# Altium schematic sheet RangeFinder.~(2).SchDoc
size A
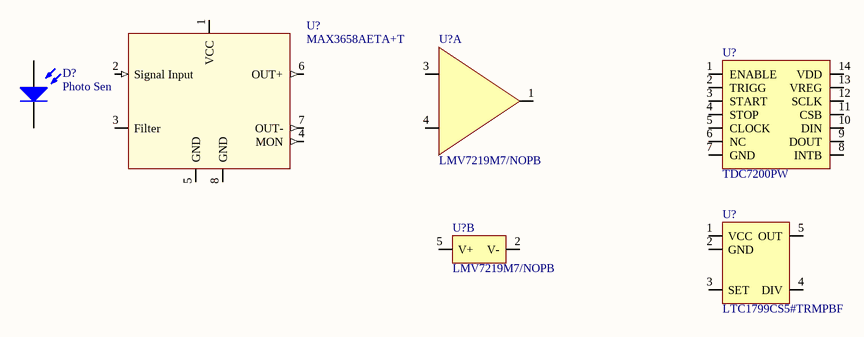
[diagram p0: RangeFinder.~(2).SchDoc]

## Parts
(Parts that share a designator on the sheet are numbered #1, #2 ... from top to bottom, then left to right.)
D?  Photo Sen  [PIN2]
U?#1  MAX3658AETA+T
U?#2  LMV7219M7/NOPB  (part A of 2)
U?#3  TDC7200PW
U?#4  LMV7219M7/NOPB  (part B of 2)
U?#5  LTC1799CS5#TRMPBF

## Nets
GND: U?#1.9(PAD)

Not connected (* = marked no-connect by the designer): D? 1(A) 2(K); U?#1 1(VCC) 2(Signal_Input) 3(Filter) 4(MON) 5(GND) 6(OUT+) 7(OUT-) 8(GND); U?#2 1(OUT) 3(IN+) 4(IN-); U?#3 1(ENABLE) 2(TRIGG) 3(START) 4(STOP) 5(CLOCK) 6(NC) 7(GND) 8(INTB) 9(DOUT) 10(DIN) 11(CSB) 12(SCLK) 13(VREG) 14(VDD); U?#4 2(V-) 5(V+); U?#5 1(VCC) 2(GND) 3(SET) 4(DIV) 5(OUT)

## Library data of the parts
D? = Photo Sen: Photosensitive Diode
U?#1 = MAX3658AETA+T: IC AMP TRANSIMPEDANCE 8-TDFN
U?#2 U?#4 = LMV7219M7/NOPB: IC COMPARATOR SC-70-5
U?#3 = TDC7200PW: STATIC ULTRASONIC FLOWMETER AF
U?#5 = LTC1799CS5#TRMPBF: IC OSC SILICON PROG TSOT23-5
